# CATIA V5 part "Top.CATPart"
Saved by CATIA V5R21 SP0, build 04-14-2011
Part number: Part1.3
Material "Fire Red": density 7860 kg/m3, Young's modulus 2e+11 Pa, Poisson ratio 0.266
Bounding box of the stored display mesh (mm): x 0 to 25, y -18.49 to 18.49, z 51.4 to 66.4
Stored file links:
  G:\CATIA\Class\Project_2\Top.CATPart
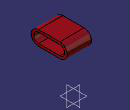
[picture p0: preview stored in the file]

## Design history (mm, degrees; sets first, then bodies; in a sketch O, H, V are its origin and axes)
Body1 (main body), material "Fire Red"
  Sketch1 on yz-plane, origin (0, 0, 0), H (0, 1, 0), V (0, 0, 1)
    construction line L1 (11, 58.9) -> (-11, 58.9)
    point P1 (11, 58.9)
    point P2 (-11, 58.9)
    line L2 (11, 51.4) -> (-11, 51.4)
    line L3 (-11, 66.4) -> (11, 66.4)
    arc A1 centre (-11, 58.9) radius 7.5 from (-11, 51.4) to (-11, 66.4) cw
    arc A2 centre (11, 58.9) radius 7.5 from (11, 66.4) to (11, 51.4) cw
    construction line L4 (11, 58.9) -> (-11, 58.9)
    line L5 (11, 53.9) -> (-11, 53.9)
    line L6 (-11, 63.9) -> (11, 63.9)
    arc A3 centre (-11, 58.9) radius 5 from (-11, 53.9) to (-11, 63.9) cw
    arc A4 centre (11, 58.9) radius 5 from (11, 63.9) to (11, 53.9) cw
    distance L1 L2 = 7.5
    distance L4 L5 = 5
    distance L4 H = 58.9
    distance P1 V = 11
    distance P2 V = 11
    horizontal: L1 H, L4 H
    tangency: A1 L2, A2 L2, A1 L3, A2 L3, A3 L5, A4 L5, A3 L6, A4 L6
  Pad1: profile Sketch1, direction (1, 0, 0), length 25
